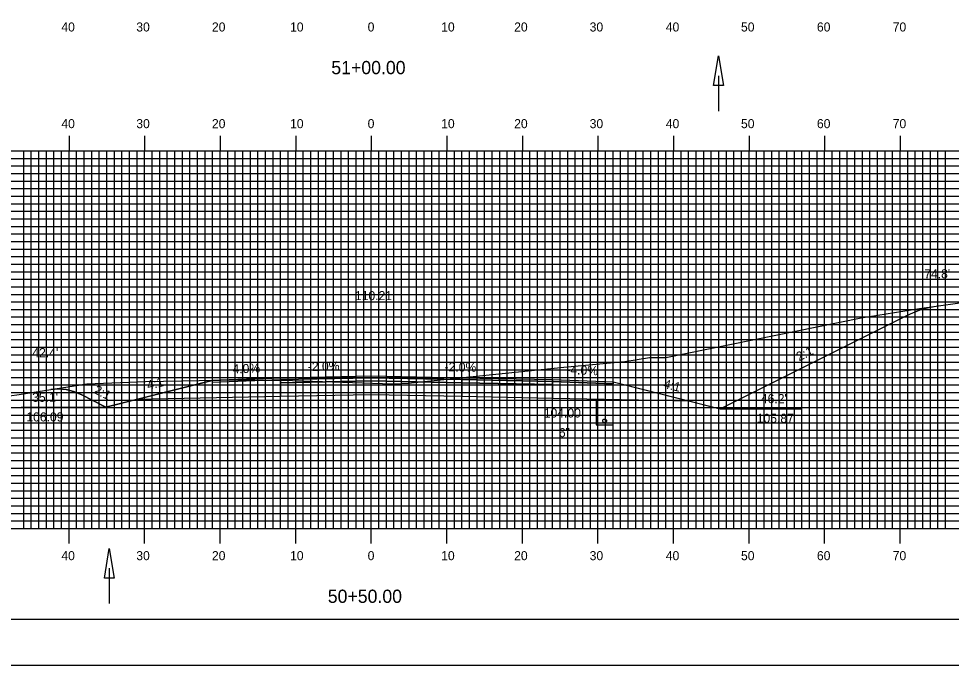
# Model space of a CAD drawing. Extents: x 1755495 to 1755838, y 442591 to 442811.
# Drawn here: x 1755613.9 to 1755737.3, y 442590.5 to 442676.2 of the extents above; entities that cross this region are included whole.
import ezdxf

# ---------------------------------------------------------------- set-up
doc = ezdxf.new("R2010")
doc.units = 0
for name, color, linetype in [('ANNOTATION', 7, 'Continuous'), ('BORDER', 7, 'Continuous'), ('D_Drainage_Ditch_Line', 7, 'Continuous'), ('D_Roadway_Centerline', 7, 'Continuous'), ('D_Roadway_Centerline_Text', 7, 'Continuous'), ('D_Roadway_Edge_Shoulder', 7, 'Continuous'), ('D_Roadway_Edge_TW', 7, 'Continuous'), ('D_Roadway_Pavement', 7, 'Continuous'), ('D_Roadway_SlopeLines', 7, 'Continuous'), ('D_Roadway_SubGrade', 7, 'Continuous'), ('D_Text_Standard', 7, 'Continuous'), ('H_V ANNOTATION', 7, 'Continuous'), ('MAJOR', 7, 'Continuous'), ('MINOR', 7, 'Continuous'), ('PDRAIN', 7, 'Continuous'), ('PLOT BOUNDARY', 7, 'Continuous'), ('S_Roadway_Centerline', 7, 'Continuous')]:
    doc.layers.add(name, color=color, linetype=linetype)

msp = doc.modelspace()

# ---------------------------------------------------------------- linework, layer by layer
at = {"layer": 'BORDER'}
msp.add_lwpolyline([(1755510.94, 442596.67), (1755830.94, 442596.67), (1755830.94, 442806.67), (1755510.94, 442806.67)], close=True, dxfattribs=at)
at = {"layer": 'D_Drainage_Ditch_Line'}
for p, q in [((1755706.51, 442668.62), (1755706.51, 442663.92)), ((1755625.86, 442603.42), (1755625.86, 442598.72))]:
    msp.add_line(p, q, dxfattribs=at)
for points in [[(1755707.17, 442667.31), (1755705.85, 442667.31), (1755706.51, 442671.24)], [(1755626.52, 442602.11), (1755625.21, 442602.11), (1755625.86, 442606.04)]]:
    msp.add_lwpolyline(points, close=True, dxfattribs=at)
at = {"layer": 'D_Roadway_Centerline'}
msp.add_lwpolyline([(1755618.14, 442627.07), (1755619.14, 442627.15), (1755620.14, 442627.06), (1755621.14, 442626.81), (1755622.14, 442626.39), (1755625.42, 442624.75), (1755629.42, 442625.75), (1755639.5, 442628.27), (1755648.54, 442628.63), (1755660.54, 442628.87), (1755672.54, 442628.63), (1755684.54, 442628.39), (1755692.54, 442628.07), (1755702.72, 442625.53), (1755706.72, 442624.53), (1755731.31, 442636.83), (1755732.31, 442637.28), (1755733.31, 442637.65), (1755734.31, 442637.93), (1755735.31, 442638.11)], dxfattribs=at)
at = {"layer": 'D_Roadway_Edge_Shoulder'}
for points in [[(1755648.54, 442628.63), (1755639.5, 442628.27), (1755639.5, 442628.02), (1755648.54, 442628.38)], [(1755684.54, 442628.39), (1755692.54, 442628.07), (1755692.54, 442627.82), (1755684.54, 442628.14)]]:
    msp.add_lwpolyline(points, close=True, dxfattribs=at)
at = {"layer": 'D_Roadway_Edge_TW'}
for points in [[(1755648.54, 442628.38), (1755648.54, 442628.63), (1755660.54, 442628.87), (1755672.54, 442628.63), (1755672.54, 442628.38), (1755660.54, 442628.62)], [(1755672.54, 442628.63), (1755684.54, 442628.39), (1755684.54, 442628.14), (1755672.54, 442628.38)]]:
    msp.add_lwpolyline(points, close=True, dxfattribs=at)
at = {"layer": 'D_Roadway_Pavement'}
for points in [[(1755648.54, 442627.97), (1755648.54, 442628.38), (1755660.54, 442628.62), (1755672.54, 442628.38), (1755672.54, 442627.97), (1755660.54, 442628.21)], [(1755672.54, 442628.38), (1755684.54, 442628.14), (1755684.54, 442627.73), (1755672.54, 442627.97)]]:
    msp.add_lwpolyline(points, close=True, dxfattribs=at)
msp.add_lwpolyline([(1755684.54, 442628.14), (1755684.54, 442627.73)], dxfattribs=at)
msp.add_lwpolyline([(1755684.54, 442628.14), (1755684.54, 442627.73)], dxfattribs=at)
msp.add_lwpolyline([(1755684.54, 442628.14), (1755684.54, 442627.73)], dxfattribs=at)
at = {"layer": 'D_Roadway_SlopeLines'}
for points in [[(1755706.72, 442624.53), (1755731.31, 442636.83), (1755732.31, 442637.28), (1755733.31, 442637.65), (1755734.31, 442637.93), (1755735.31, 442638.11)], [(1755639.5, 442628.27), (1755625.42, 442624.75)], [(1755692.54, 442628.07), (1755706.72, 442624.53)], [(1755625.42, 442624.75), (1755622.14, 442626.39), (1755621.14, 442626.81), (1755620.14, 442627.06), (1755619.14, 442627.15), (1755618.14, 442627.07)]]:
    msp.add_lwpolyline(points, dxfattribs=at)
at = {"layer": 'D_Roadway_SubGrade'}
for points in [[(1755639.5, 442628.02), (1755648.54, 442628.38), (1755648.54, 442627.97), (1755648.54, 442626.13), (1755629.42, 442625.75), (1755639.5, 442628.27)], [(1755648.54, 442626.13), (1755648.54, 442627.97), (1755660.54, 442628.21), (1755672.54, 442627.97), (1755672.54, 442626.13), (1755660.54, 442626.37)], [(1755672.54, 442627.97), (1755684.54, 442627.73), (1755684.54, 442625.89), (1755672.54, 442626.13)], [(1755684.54, 442627.73), (1755684.54, 442628.14), (1755692.54, 442627.82), (1755692.54, 442628.07), (1755702.72, 442625.53), (1755684.54, 442625.89)], [(1755684.54, 442627.73), (1755684.54, 442628.14), (1755692.54, 442627.82), (1755692.54, 442628.07), (1755702.72, 442625.53), (1755684.54, 442625.89)]]:
    msp.add_lwpolyline(points, close=True, dxfattribs=at)
at = {"layer": 'MAJOR'}
for p, q in [((1755620.54, 442660.67), (1755620.54, 442658.67)), ((1755630.54, 442660.67), (1755630.54, 442658.67)), ((1755640.54, 442660.67), (1755640.54, 442658.67)), ((1755650.54, 442660.67), (1755650.54, 442658.67)), ((1755660.54, 442660.67), (1755660.54, 442658.67)), ((1755670.54, 442660.67), (1755670.54, 442658.67)), ((1755680.54, 442660.67), (1755680.54, 442658.67)), ((1755690.54, 442660.67), (1755690.54, 442658.67)), ((1755700.54, 442660.67), (1755700.54, 442658.67)), ((1755710.54, 442660.67), (1755710.54, 442658.67)), ((1755720.54, 442660.67), (1755720.54, 442658.67)), ((1755730.54, 442660.67), (1755730.54, 442658.67)), ((1755520.54, 442658.67), (1755800.54, 442658.67)), ((1755520.54, 442658.67), (1755800.54, 442658.67)), ((1755620.54, 442608.67), (1755620.54, 442658.67)), ((1755630.54, 442608.67), (1755630.54, 442658.67)), ((1755640.54, 442608.67), (1755640.54, 442658.67)), ((1755650.54, 442608.67), (1755650.54, 442658.67)), ((1755660.54, 442608.67), (1755660.54, 442658.67)), ((1755670.54, 442608.67), (1755670.54, 442658.67)), ((1755680.54, 442608.67), (1755680.54, 442658.67)), ((1755690.54, 442608.67), (1755690.54, 442658.67)), ((1755700.54, 442608.67), (1755700.54, 442658.67)), ((1755710.54, 442608.67), (1755710.54, 442658.67)), ((1755720.54, 442608.67), (1755720.54, 442658.67)), ((1755730.54, 442608.67), (1755730.54, 442658.67)), ((1755520.54, 442653.67), (1755800.54, 442653.67)), ((1755520.54, 442648.67), (1755800.54, 442648.67)), ((1755520.54, 442643.67), (1755800.54, 442643.67)), ((1755520.54, 442638.67), (1755800.54, 442638.67)), ((1755520.54, 442633.67), (1755800.54, 442633.67)), ((1755520.54, 442628.67), (1755800.54, 442628.67)), ((1755520.54, 442623.67), (1755800.54, 442623.67)), ((1755520.54, 442618.67), (1755800.54, 442618.67)), ((1755520.54, 442613.67), (1755800.54, 442613.67)), ((1755520.54, 442608.67), (1755800.54, 442608.67)), ((1755520.54, 442608.67), (1755800.54, 442608.67)), ((1755620.54, 442606.66), (1755620.54, 442608.67)), ((1755630.54, 442606.66), (1755630.54, 442608.67)), ((1755640.54, 442606.66), (1755640.54, 442608.67)), ((1755650.54, 442606.66), (1755650.54, 442608.67)), ((1755660.54, 442606.66), (1755660.54, 442608.67)), ((1755670.54, 442606.66), (1755670.54, 442608.67)), ((1755680.54, 442606.66), (1755680.54, 442608.67)), ((1755690.54, 442606.66), (1755690.54, 442608.67)), ((1755700.54, 442606.66), (1755700.54, 442608.67)), ((1755710.54, 442606.66), (1755710.54, 442608.67)), ((1755720.54, 442606.66), (1755720.54, 442608.67)), ((1755730.54, 442606.66), (1755730.54, 442608.67))]:
    msp.add_line(p, q, dxfattribs=at)
at = {"layer": 'MINOR'}
for p, q in [((1755614.54, 442608.67), (1755614.54, 442658.67)), ((1755615.54, 442608.67), (1755615.54, 442658.67)), ((1755616.54, 442608.67), (1755616.54, 442658.67)), ((1755617.54, 442608.67), (1755617.54, 442658.67)), ((1755618.54, 442608.67), (1755618.54, 442658.67)), ((1755619.54, 442608.67), (1755619.54, 442658.67)), ((1755621.54, 442608.67), (1755621.54, 442658.67)), ((1755622.54, 442608.67), (1755622.54, 442658.67)), ((1755623.54, 442608.67), (1755623.54, 442658.67)), ((1755624.54, 442608.67), (1755624.54, 442658.67)), ((1755625.54, 442608.67), (1755625.54, 442658.67)), ((1755626.54, 442608.67), (1755626.54, 442658.67)), ((1755627.54, 442608.67), (1755627.54, 442658.67)), ((1755628.54, 442608.67), (1755628.54, 442658.67)), ((1755629.54, 442608.67), (1755629.54, 442658.67)), ((1755631.54, 442608.67), (1755631.54, 442658.67)), ((1755632.54, 442608.67), (1755632.54, 442658.67)), ((1755633.54, 442608.67), (1755633.54, 442658.67)), ((1755634.54, 442608.67), (1755634.54, 442658.67)), ((1755635.54, 442608.67), (1755635.54, 442658.67)), ((1755636.54, 442608.67), (1755636.54, 442658.67)), ((1755637.54, 442608.67), (1755637.54, 442658.67)), ((1755638.54, 442608.67), (1755638.54, 442658.67)), ((1755639.54, 442608.67), (1755639.54, 442658.67)), ((1755641.54, 442608.67), (1755641.54, 442658.67)), ((1755642.54, 442608.67), (1755642.54, 442658.67)), ((1755643.54, 442608.67), (1755643.54, 442658.67)), ((1755644.54, 442608.67), (1755644.54, 442658.67)), ((1755645.54, 442608.67), (1755645.54, 442658.67)), ((1755646.54, 442608.67), (1755646.54, 442658.67)), ((1755647.54, 442608.67), (1755647.54, 442658.67)), ((1755648.54, 442608.67), (1755648.54, 442658.67)), ((1755649.54, 442608.67), (1755649.54, 442658.67)), ((1755651.54, 442608.67), (1755651.54, 442658.67)), ((1755652.54, 442608.67), (1755652.54, 442658.67)), ((1755653.54, 442608.67), (1755653.54, 442658.67)), ((1755654.54, 442608.67), (1755654.54, 442658.67)), ((1755655.54, 442608.67), (1755655.54, 442658.67)), ((1755656.54, 442608.67), (1755656.54, 442658.67)), ((1755657.54, 442608.67), (1755657.54, 442658.67)), ((1755658.54, 442608.67), (1755658.54, 442658.67)), ((1755659.54, 442608.67), (1755659.54, 442658.67)), ((1755661.54, 442608.67), (1755661.54, 442658.67)), ((1755662.54, 442608.67), (1755662.54, 442658.67)), ((1755663.54, 442608.67), (1755663.54, 442658.67)), ((1755664.54, 442608.67), (1755664.54, 442658.67)), ((1755665.54, 442608.67), (1755665.54, 442658.67)), ((1755666.54, 442608.67), (1755666.54, 442658.67)), ((1755667.54, 442608.67), (1755667.54, 442658.67)), ((1755668.54, 442608.67), (1755668.54, 442658.67)), ((1755669.54, 442608.67), (1755669.54, 442658.67)), ((1755671.54, 442608.67), (1755671.54, 442658.67)), ((1755672.54, 442608.67), (1755672.54, 442658.67)), ((1755673.54, 442608.67), (1755673.54, 442658.67)), ((1755674.54, 442608.67), (1755674.54, 442658.67)), ((1755675.54, 442608.67), (1755675.54, 442658.67)), ((1755676.54, 442608.67), (1755676.54, 442658.67)), ((1755677.54, 442608.67), (1755677.54, 442658.67)), ((1755678.54, 442608.67), (1755678.54, 442658.67)), ((1755679.54, 442608.67), (1755679.54, 442658.67)), ((1755681.54, 442608.67), (1755681.54, 442658.67)), ((1755682.54, 442608.67), (1755682.54, 442658.67)), ((1755683.54, 442608.67), (1755683.54, 442658.67)), ((1755684.54, 442608.67), (1755684.54, 442658.67)), ((1755685.54, 442608.67), (1755685.54, 442658.67)), ((1755686.54, 442608.67), (1755686.54, 442658.67)), ((1755687.54, 442608.67), (1755687.54, 442658.67)), ((1755688.54, 442608.67), (1755688.54, 442658.67)), ((1755689.54, 442608.67), (1755689.54, 442658.67)), ((1755691.54, 442608.67), (1755691.54, 442658.67)), ((1755692.54, 442608.67), (1755692.54, 442658.67)), ((1755693.54, 442608.67), (1755693.54, 442658.67)), ((1755694.54, 442608.67), (1755694.54, 442658.67)), ((1755695.54, 442608.67), (1755695.54, 442658.67)), ((1755696.54, 442608.67), (1755696.54, 442658.67)), ((1755697.54, 442608.67), (1755697.54, 442658.67)), ((1755698.54, 442608.67), (1755698.54, 442658.67)), ((1755699.54, 442608.67), (1755699.54, 442658.67)), ((1755701.54, 442608.67), (1755701.54, 442658.67)), ((1755702.54, 442608.67), (1755702.54, 442658.67)), ((1755703.54, 442608.67), (1755703.54, 442658.67)), ((1755704.54, 442608.67), (1755704.54, 442658.67)), ((1755705.54, 442608.67), (1755705.54, 442658.67)), ((1755706.54, 442608.67), (1755706.54, 442658.67)), ((1755707.54, 442608.67), (1755707.54, 442658.67)), ((1755708.54, 442608.67), (1755708.54, 442658.67)), ((1755709.54, 442608.67), (1755709.54, 442658.67)), ((1755711.54, 442608.67), (1755711.54, 442658.67)), ((1755712.54, 442608.67), (1755712.54, 442658.67)), ((1755713.54, 442608.67), (1755713.54, 442658.67)), ((1755714.54, 442608.67), (1755714.54, 442658.67)), ((1755715.54, 442608.67), (1755715.54, 442658.67)), ((1755716.54, 442608.67), (1755716.54, 442658.67)), ((1755717.54, 442608.67), (1755717.54, 442658.67)), ((1755718.54, 442608.67), (1755718.54, 442658.67)), ((1755719.54, 442608.67), (1755719.54, 442658.67)), ((1755721.54, 442608.67), (1755721.54, 442658.67)), ((1755722.54, 442608.67), (1755722.54, 442658.67)), ((1755723.54, 442608.67), (1755723.54, 442658.67)), ((1755724.54, 442608.67), (1755724.54, 442658.67)), ((1755725.54, 442608.67), (1755725.54, 442658.67)), ((1755726.54, 442608.67), (1755726.54, 442658.67)), ((1755727.54, 442608.67), (1755727.54, 442658.67)), ((1755728.54, 442608.67), (1755728.54, 442658.67)), ((1755729.54, 442608.67), (1755729.54, 442658.67)), ((1755731.54, 442608.67), (1755731.54, 442658.67)), ((1755732.54, 442608.67), (1755732.54, 442658.67)), ((1755733.54, 442608.67), (1755733.54, 442658.67)), ((1755734.54, 442608.67), (1755734.54, 442658.67)), ((1755735.54, 442608.67), (1755735.54, 442658.67)), ((1755736.54, 442608.67), (1755736.54, 442658.67)), ((1755520.54, 442657.67), (1755800.54, 442657.67)), ((1755520.54, 442656.67), (1755800.54, 442656.67)), ((1755520.54, 442655.67), (1755800.54, 442655.67)), ((1755520.54, 442654.67), (1755800.54, 442654.67)), ((1755520.54, 442652.67), (1755800.54, 442652.67)), ((1755520.54, 442651.67), (1755800.54, 442651.67)), ((1755520.54, 442650.67), (1755800.54, 442650.67)), ((1755520.54, 442649.67), (1755800.54, 442649.67)), ((1755520.54, 442647.67), (1755800.54, 442647.67)), ((1755520.54, 442646.67), (1755800.54, 442646.67)), ((1755520.54, 442645.67), (1755800.54, 442645.67)), ((1755520.54, 442644.67), (1755800.54, 442644.67)), ((1755520.54, 442642.67), (1755800.54, 442642.67)), ((1755520.54, 442641.67), (1755800.54, 442641.67)), ((1755520.54, 442640.67), (1755800.54, 442640.67)), ((1755520.54, 442639.67), (1755800.54, 442639.67)), ((1755520.54, 442637.67), (1755800.54, 442637.67)), ((1755520.54, 442636.67), (1755800.54, 442636.67)), ((1755520.54, 442635.67), (1755800.54, 442635.67)), ((1755520.54, 442634.67), (1755800.54, 442634.67)), ((1755520.54, 442632.67), (1755800.54, 442632.67)), ((1755520.54, 442631.67), (1755800.54, 442631.67)), ((1755520.54, 442630.67), (1755800.54, 442630.67)), ((1755520.54, 442629.67), (1755800.54, 442629.67)), ((1755520.54, 442627.67), (1755800.54, 442627.67)), ((1755520.54, 442626.67), (1755800.54, 442626.67)), ((1755520.54, 442625.67), (1755800.54, 442625.67)), ((1755520.54, 442624.67), (1755800.54, 442624.67)), ((1755520.54, 442622.67), (1755800.54, 442622.67)), ((1755520.54, 442621.67), (1755800.54, 442621.67)), ((1755520.54, 442620.67), (1755800.54, 442620.67)), ((1755520.54, 442619.67), (1755800.54, 442619.67)), ((1755520.54, 442617.67), (1755800.54, 442617.67)), ((1755520.54, 442616.67), (1755800.54, 442616.67)), ((1755520.54, 442615.67), (1755800.54, 442615.67)), ((1755520.54, 442614.67), (1755800.54, 442614.67)), ((1755520.54, 442612.67), (1755800.54, 442612.67)), ((1755520.54, 442611.67), (1755800.54, 442611.67)), ((1755520.54, 442610.67), (1755800.54, 442610.67)), ((1755520.54, 442609.67), (1755800.54, 442609.67))]:
    msp.add_line(p, q, dxfattribs=at)
at = {"layer": 'PDRAIN'}
for p, q in [((1755614.2, 442624.75), (1755625.42, 442624.75)), ((1755706.72, 442624.53), (1755717.49, 442624.53)), ((1755682.7, 442622.66), (1755691.42, 442622.66))]:
    msp.add_line(p, q, dxfattribs=at)
msp.add_lwpolyline([(1755690.29, 442625.78), (1755690.29, 442622.41), (1755692.54, 442622.41), (1755692.54, 442625.73)], dxfattribs=at)
msp.add_circle((1755691.42, 442622.91), 0.25, dxfattribs=at)
at = {"layer": 'PLOT BOUNDARY'}
msp.add_lwpolyline([(1755494.76, 442590.55), (1755834.76, 442590.55), (1755834.76, 442810.55), (1755494.76, 442810.55)], close=True, dxfattribs=at)
at = {"layer": 'S_Roadway_Centerline'}
msp.add_lwpolyline([(1755603.68, 442624.99), (1755613.92, 442626.39), (1755622.91, 442627.84), (1755630.67, 442628.12), (1755642.51, 442628.33), (1755650.1, 442628.26), (1755662.02, 442627.85), (1755663.48, 442627.82), (1755665.43, 442627.89), (1755686.03, 442630.02), (1755694.09, 442630.78), (1755697.38, 442631.29), (1755699.52, 442631.3), (1755725.38, 442636.54), (1755733.09, 442637.8), (1755738.12, 442638.52), (1755761.32, 442643.07), (1755771.13, 442645.16), (1755776.81, 442646.28), (1755780.62, 442646.9), (1755791.38, 442649.24), (1755792.27, 442649.15), (1755795.64, 442649.41), (1755800.54, 442650.07)], dxfattribs=at)

# ---------------------------------------------------------------- texts
at = {"layer": 'ANNOTATION'}
for s, rotation, p in [('2:1', 26.5651, (1755717.16, 442630.79)), ('-4.0%', 2.2906, (1755641.66, 442629.16)), ('-2.0%', 1.1458, (1755652.15, 442629.51)), ('-2.0%', 358.8542, (1755670.23, 442629.48)), ('-4.0%', 357.7094, (1755686.34, 442629.12)), ('4:1', 14.0362, (1755631, 442627.01)), ('4:1', 345.9638, (1755699.14, 442627.29)), ('2:1', 333.4349, (1755623.71, 442626.64))]:
    msp.add_text(s, height=1.2, rotation=rotation, dxfattribs=at).set_placement(p)
for s, p in [("35.1'", (1755615.66, 442625.44)), ("46.2'", (1755712.1, 442625.26)), ('104.00', (1755683.37, 442623.36)), ('106.09', (1755614.89, 442622.84)), ('105.87', (1755711.55, 442622.66)), ('6"', (1755685.36, 442620.76))]:
    msp.add_text(s, height=1.2, dxfattribs=at).set_placement(p)
at = {"layer": 'D_Roadway_Centerline'}
for s in ['C', 'L']:
    msp.add_text(s, height=0.0146, dxfattribs=at).set_placement((1755660.54, 442628.87))
at = {"layer": 'D_Roadway_Centerline_Text'}
msp.add_text('110.21', height=1.2, dxfattribs=at).set_placement((1755658.38, 442638.9))
at = {"layer": 'D_Text_Standard'}
for s, p in [("74.8'", (1755733.72, 442641.79)), ("42.4'", (1755615.68, 442631.35))]:
    msp.add_text(s, height=1.2, dxfattribs=at).set_placement(p)
at = {"layer": 'H_V ANNOTATION'}
for s, height, p in [('40', 1.2, (1755619.52, 442674.47)), ('30', 1.2, (1755629.44, 442674.47)), ('20', 1.2, (1755639.45, 442674.47)), ('10', 1.2, (1755649.79, 442674.47)), ('0', 1.2, (1755660.06, 442674.47)), ('10', 1.2, (1755669.79, 442674.47)), ('20', 1.2, (1755679.45, 442674.47)), ('30', 1.2, (1755689.44, 442674.47)), ('40', 1.2, (1755699.52, 442674.47)), ('50', 1.2, (1755709.47, 442674.47)), ('60', 1.2, (1755719.52, 442674.47)), ('70', 1.2, (1755729.55, 442674.47)), ('51+00.00', 1.75, (1755655.25, 442668.82)), ('40', 1.2, (1755619.52, 442661.67)), ('30', 1.2, (1755629.44, 442661.67)), ('20', 1.2, (1755639.45, 442661.67)), ('10', 1.2, (1755649.79, 442661.67)), ('0', 1.2, (1755660.06, 442661.67)), ('10', 1.2, (1755669.79, 442661.67)), ('20', 1.2, (1755679.45, 442661.67)), ('30', 1.2, (1755689.44, 442661.67)), ('40', 1.2, (1755699.52, 442661.67)), ('50', 1.2, (1755709.47, 442661.67)), ('60', 1.2, (1755719.52, 442661.67)), ('70', 1.2, (1755729.55, 442661.67)), ('40', 1.2, (1755619.52, 442604.47)), ('30', 1.2, (1755629.44, 442604.47)), ('20', 1.2, (1755639.45, 442604.47)), ('10', 1.2, (1755649.79, 442604.47)), ('0', 1.2, (1755660.06, 442604.47)), ('10', 1.2, (1755669.79, 442604.47)), ('20', 1.2, (1755679.45, 442604.47)), ('30', 1.2, (1755689.44, 442604.47)), ('40', 1.2, (1755699.52, 442604.47)), ('50', 1.2, (1755709.47, 442604.47)), ('60', 1.2, (1755719.52, 442604.47)), ('70', 1.2, (1755729.55, 442604.47)), ('50+50.00', 1.75, (1755654.78, 442598.82))]:
    msp.add_text(s, height=height, dxfattribs=at).set_placement(p)

doc.saveas('drawing.dxf')
